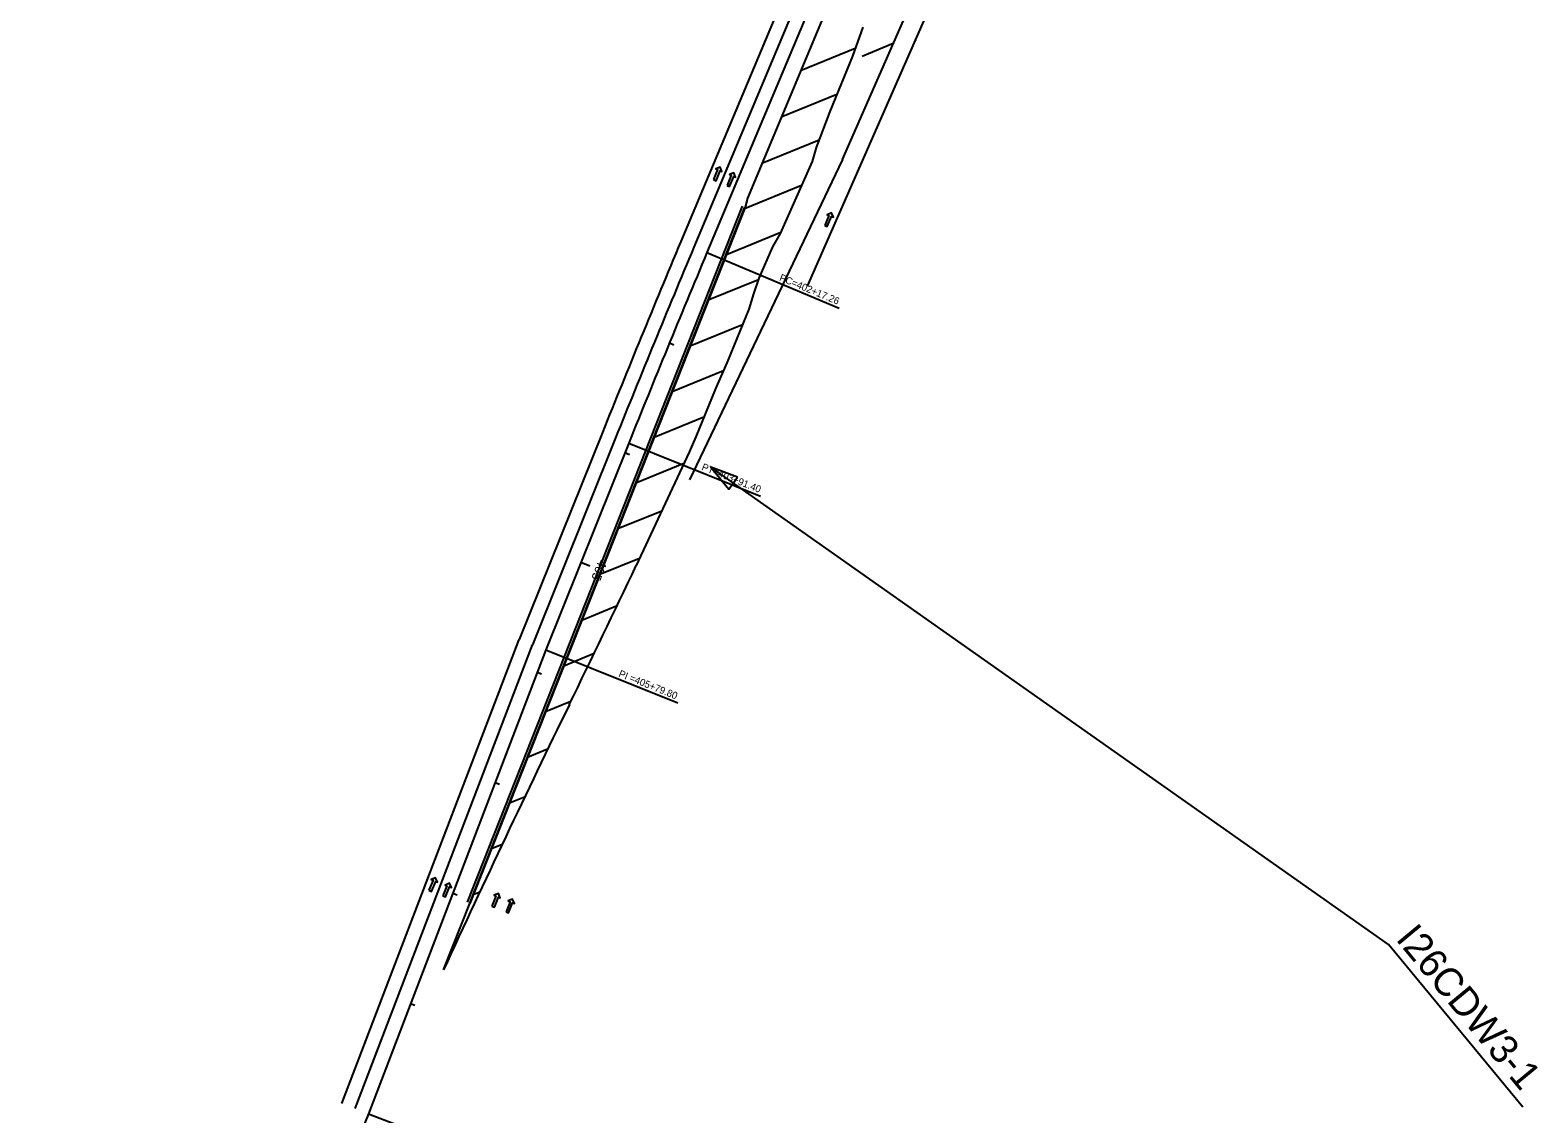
# Model space of a CAD drawing. Extents: x 1966356 to 1974207, y 790684 to 800034.
# Drawn here: x 1967884 to 1969159, y 795746 to 796663 of the extents above; entities that cross this region are included whole.
import ezdxf

# ---------------------------------------------------------------- set-up
doc = ezdxf.new("R2010")
doc.units = 0
for name, color, linetype in [('RD_EX_Pavement_Markings', 7, 'Continuous'), ('RD_HC_Cl', 7, 'Continuous'), ('RD_HC_Data', 7, 'Continuous'), ('RD_HC_Data_Tic', 7, 'Continuous'), ('RD_HC_TX_Sta50', 7, 'Continuous'), ('RD_PD_ALT5_LnLine', 7, 'Continuous'), ('RD_PD_ALT5_TrvlWay', 7, 'Continuous'), ('RD_TX_RoadID', 7, 'Continuous'), ('TR_WZ_Temp Conc Barrier', 7, 'Continuous')]:
    doc.layers.add(name, color=color, linetype=linetype)

msp = doc.modelspace()

# ---------------------------------------------------------------- linework, layer by layer
at = {"layer": 'RD_EX_Pavement_Markings'}
for p, q in [((1968725.9, 797177.9), (1968434.7, 796483.7)), ((1968737, 797173.5), (1968445.8, 796479)), ((1968748.2, 797169), (1968456.8, 796474.4)), ((1968368.4, 796322.2), (1968298.1, 796147.2)), ((1968379.6, 796317.8), (1968309.3, 796142.8)), ((1968390.7, 796313.3), (1968320.5, 796138.5))]:
    msp.add_line(p, q, dxfattribs=at)
for radius in [11453.2, 11441.2, 11429.2]:
    msp.add_arc((1978996.5, 792053.9), radius, 157.24601, 158.11901, dxfattribs=at)
at = {"layer": 'RD_HC_Cl'}
for p, q in [((1968390.7, 796313.3), (1968320.5, 796138.5)), ((1968320.5, 796138.5), (1968170.5, 795746.2))]:
    msp.add_line(p, q, dxfattribs=at)
msp.add_arc((1978996.5, 792053.9), 11429.2, 157.24601, 158.11901, dxfattribs=at)
at = {"layer": 'RD_HC_Data'}
for p, q in [((1968456.8, 796474.4), (1968568.7, 796427.4)), ((1968390.7, 796313.3), (1968502.2, 796268.5)), ((1968320.5, 796138.5), (1968432.2, 796093.6)), ((1968170.5, 795746.2), (1968288.6, 795701))]:
    msp.add_line(p, q, dxfattribs=at)
at = {"layer": 'RD_HC_Data_Tic'}
for p, q in [((1968425.1, 796398), (1968428.8, 796396.4)), ((1968387.5, 796305.3), (1968391.2, 796303.8)), ((1968350.2, 796212.5), (1968357.7, 796209.5)), ((1968313.3, 796119.6), (1968317, 796118.2)), ((1968277.6, 796026.2), (1968281.3, 796024.8)), ((1968241.8, 795932.8), (1968245.6, 795931.3)), ((1968206.1, 795839.4), (1968209.9, 795837.9))]:
    msp.add_line(p, q, dxfattribs=at)
at = {"layer": 'RD_PD_ALT5_LnLine'}
for p, q in [((1968571.4, 796553.1), (1968860.3, 797212)), ((1968541.9, 796446), (1968875, 797205.5)), ((1968557.8, 796680.2), (1968491, 796520.4)), ((1968614.4, 796651.2), (1968588, 796640.4)), ((1968633.1, 796653.8), (1968633.2, 796653.5)), ((1968582.2, 796647), (1968536, 796628.1)), ((1968566.7, 796608.2), (1968519.7, 796589)), ((1968551.6, 796569.6), (1968503.3, 796549.9)), ((1968571.4, 796553.1), (1968442, 796282.4)), ((1968536.8, 796531.2), (1968488.5, 796511.4)), ((1968489, 796512.8), (1968256.4, 795924.1)), ((1968491, 796520.4), (1968489, 796512.8)), ((1968519.2, 796491.5), (1968473.2, 796472.7)), ((1968500.3, 796451.4), (1968457.9, 796434.1)), ((1968486.9, 796413.5), (1968442.6, 796395.4)), ((1968470.8, 796374.5), (1968427.3, 796356.7)), ((1968454.1, 796335.3), (1968412.1, 796318.1)), ((1968441.9, 796305.8), (1968396.9, 796209.7)), ((1968437.3, 796296), (1968396.8, 796279.4)), ((1968418.6, 796255.9), (1968381.5, 796240.8)), ((1968399.8, 796215.8), (1968366.2, 796202.1)), ((1968380.8, 796175.6), (1968350.9, 796163.4)), ((1968159.3, 795750.5), (1968309.3, 796142.8)), ((1968361.4, 796135.3), (1968335.7, 796124.8)), ((1968341.7, 796094.8), (1968320.4, 796086.1)), ((1968322, 796054.4), (1968305.1, 796047.4)), ((1968302.6, 796014), (1968289.8, 796008.8)), ((1968283.5, 795973.8), (1968274.5, 795970.1)), ((1968234.1, 795867.8), (1968256.4, 795924.1)), ((1968264.6, 795933.6), (1968259.2, 795931.4)), ((1968246, 795893.6), (1968244, 795892.8))]:
    msp.add_line(p, q, dxfattribs=at)
msp.add_lwpolyline([(1968588.5, 796665.2), (1968580, 796640.7), (1968560.7, 796593.7), (1968549.2, 796563.4), (1968545.9, 796551.6), (1968518.7, 796490.5), (1968512.1, 796479.4), (1968500.8, 796452.8), (1968496.1, 796439.6), (1968492.1, 796426.5), (1968484.7, 796407.9), (1968474.6, 796383.2), (1968463.7, 796358.7), (1968447.3, 796318.7), (1968441.9, 796305.8)], dxfattribs=at)
for points in [[(1968462.3, 796536.2), (1968464.5, 796535.2), (1968468, 796543.7), (1968469.5, 796543.1), (1968468, 796546.8), (1968464.3, 796545.3), (1968465.8, 796544.6)], [(1968473.8, 796531.3), (1968476, 796530.4), (1968479.5, 796538.9), (1968481, 796538.2), (1968479.5, 796541.9), (1968475.8, 796540.4), (1968477.3, 796539.8)], [(1968556.4, 796497.4), (1968558.6, 796496.4), (1968562.2, 796504.9), (1968563.7, 796504.3), (1968562.2, 796508), (1968558.5, 796506.4), (1968560, 796505.8)], [(1968221.7, 795935.1), (1968224, 795934.2), (1968227.4, 795942.7), (1968228.9, 795942.1), (1968227.3, 795945.8), (1968223.7, 795944.2), (1968225.2, 795943.6)], [(1968233.5, 795930.4), (1968235.7, 795929.5), (1968239.1, 795938), (1968240.7, 795937.4), (1968239.1, 795941.1), (1968235.4, 795939.5), (1968236.9, 795938.9)], [(1968274.9, 795921.7), (1968277.1, 795920.9), (1968280.5, 795929.4), (1968282, 795928.8), (1968280.5, 795932.4), (1968276.8, 795930.9), (1968278.3, 795930.3)], [(1968286.9, 795917), (1968289.1, 795916.1), (1968292.5, 795924.6), (1968294, 795924), (1968292.4, 795927.6), (1968288.8, 795926.1), (1968290.3, 795925.5)]]:
    msp.add_lwpolyline(points, close=True, dxfattribs=at)
for centre, radius, start, end in [((1959629, 800353.9), 9698, 333.93129, 334.70207), ((1977342.9, 791688), 10022, 153.93129, 155.35096)]:
    msp.add_arc(centre, radius, start, end, dxfattribs=at)
at = {"layer": 'RD_PD_ALT5_TrvlWay'}
for p, q in [((1968148.1, 795754.9), (1968298.1, 796147.2)), ((1968320.5, 796138.5), (1968170.5, 795746.2)), ((1968170.5, 795746.2), (1967884.5, 795034))]:
    msp.add_line(p, q, dxfattribs=at)
at = {"layer": 'RD_TX_RoadID'}
msp.add_line((1969146.7, 795751.8), (1969033.2, 795889.2), dxfattribs=at)
msp.add_lwpolyline([(1969033.2, 795889.2), (1968460, 796292.9)], dxfattribs=at)
msp.add_lwpolyline([(1968482.6, 796284.6), (1968460, 796292.9), (1968475.4, 796274.5)], close=True, dxfattribs=at)
at = {"layer": 'TR_WZ_Temp Conc Barrier'}
for p, q in [((1968486.7, 796513.7), (1968254, 795925)), ((1968488.5, 796512.9), (1968255.9, 795924.3))]:
    msp.add_line(p, q, dxfattribs=at)

# ---------------------------------------------------------------- texts
at = {"layer": 'RD_HC_Data'}
for s, rotation, p in [('PC=402+17.26', 337.246, (1968517.5, 796451.1)), ('PT=403+91.40', 338.119, (1968451.8, 796290.9)), ('PI =405+79.80', 338.119, (1968381.6, 796116.1))]:
    msp.add_text(s, height=6, rotation=rotation, dxfattribs=at).set_placement(p)
at = {"layer": 'RD_HC_TX_Sta50'}
msp.add_text('405', height=8, rotation=248.119, dxfattribs=at).set_placement((1968365.5, 796215.5))
at = {"layer": 'RD_TX_RoadID'}
msp.add_text('I26CDW3-1 ', height=24, rotation=309.5517, dxfattribs=at).set_placement((1969038.6, 795893.7))

doc.saveas('drawing.dxf')
